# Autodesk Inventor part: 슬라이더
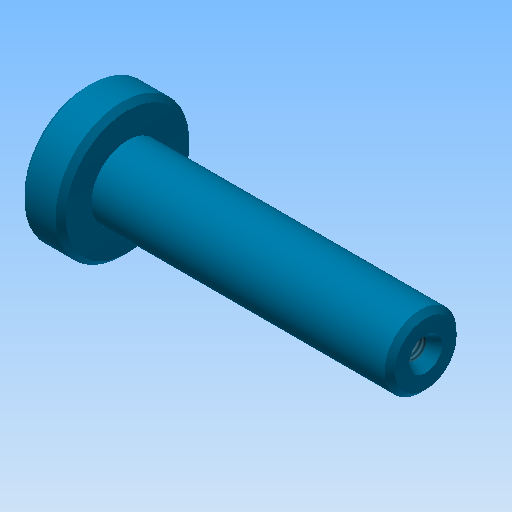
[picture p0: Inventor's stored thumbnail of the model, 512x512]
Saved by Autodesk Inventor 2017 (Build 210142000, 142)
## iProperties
Created: 2019-01
Part Number: 슬라이더
Material: 강철, 연강
Document SubType Name: Modeling
Designer: mduedu
Density: 7.86 g/cm^3
Mass: 101.006 g
Surface Area: 43.3118 cm^2
Volume: 12.8506 cm^3
Appearance: 하늘색 중간
Author: mduedu
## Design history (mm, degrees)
sketch "스케치1"
  geometry: L1 (0, 0)-(8, 0); L2 (8, 0)-(8, 13); L3 (8, 13)-(0, 13); L4 (0, 13)-(0, 0); L5 (8, 0)-(66, 0); L6 (66, 0)-(66, 7); L7 (66, 7)-(8, 7); L8 (8, 7)-(8, 0)
  constraints: 16 end point, 4 parallel, 2 horizontal, 2 perpendicular
  dimensions: "d0" = 66 distance between parallel lines of L6 L4; "d2" = 8 distance of L2.end L3.end; "d3" = 26 diameter of L3 L1; "d4" = 14 diameter of L7 L5
revolve "회전1" sketch "스케치1" stored, may be unused: angle "d5" = 90 deg
chamfer "모따기1" distance "d6" = 1; stored, may be unused: second distance "d7" = 2, angle "d8" = 45 deg
hole "구멍1" diameter "d14" = 4.134; stored, may be unused: countersink angle "d18" = 60 deg, drill point angle "d20" = 118 deg; dims "d15" = 12, "d16" = 6.3, "d17" = 2, "d19" = 15, "d26" = 10, "d27" = 10
chamfer "모따기4" distance "d24" = 1; stored, may be unused: second distance "d25" = 2, angle "d28" = 30 deg
sketch "스케치2"
  geometry: L1 (66, 2.067)-(66, -2.067) reference; L2 (66, 0)-(64, 0); L3 (64, 0)-(64, 2.067); L4 (66, 3.222)-(66, 0); L5 (66, 3.222)-(64, 2.067); L6 (51, 2.067)-(66, 2.067) reference; 1 further point
  constraints: 8 end point, 1 horizontal, 1 midpoint, 1 parallel, 1 perpendicular, 1 point on line
  dimensions: "d29" = 2 horizontal distance of L4.start L3.end; "d31" = 30 deg angle of L2 L5
revolve "회전2" sketch "스케치2" stored, may be unused: angle "d33" = 90 deg
node "솔리드1"
